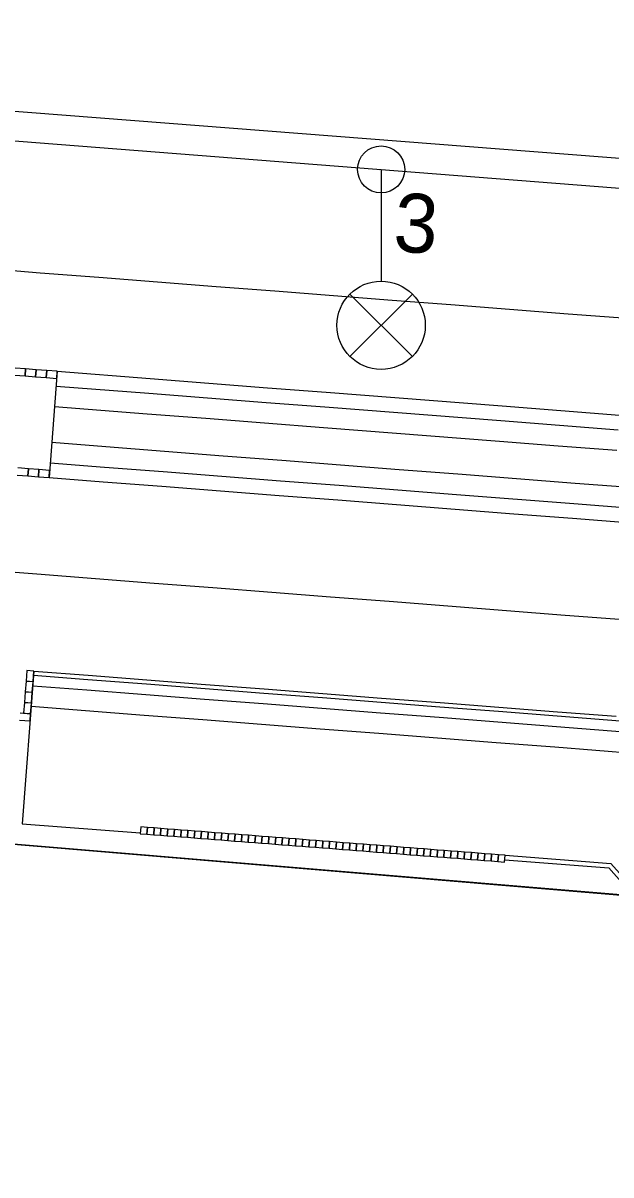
# Model space of a CAD drawing. Extents: x -669628 to -669207, y -977198 to -977075.
# Drawn here: x -669510.73 to -669500.74, y -977152.98 to -977133.39 of the extents above; entities that cross this region are included whole.
import ezdxf

# ---------------------------------------------------------------- set-up
doc = ezdxf.new("R2010")
doc.units = 0
for name, color, linetype in [('SO 01-86-01', 7, 'Continuous'), ('SO 11-10-01', 7, 'Continuous'), ('SO 11-11-01', 7, 'Continuous'), ('SO 11-12-01', 7, 'Continuous'), ('SO 11-12-02', 7, 'Continuous')]:
    doc.layers.add(name, color=color, linetype=linetype)

# ---------------------------------------------------------------- blocks, each defined once
blk = doc.blocks.new('POINT_DISPLAY')
blk.add_line((0, 0), (0, 0))

msp = doc.modelspace()

# ---------------------------------------------------------------- linework, layer by layer
at = {"layer": 'SO 01-86-01'}
for p, q in [((-669519.163, -977134.751), (-669492.657, -977136.821)), ((-669504.645, -977135.881), (-669504.645, -977137.381)), ((-669504.645, -977136.281), (-669504.645, -977137.781)), ((-669505.175, -977138), (-669504.114, -977139.061)), ((-669504.114, -977138), (-669505.175, -977139.061)), ((-669504.645, -977139.281), (-669504.645, -977139.281)), ((-669445.341, -977152.857), (-669517.763, -977146.78)), ((-669445.341, -977152.857), (-669517.763, -977146.78)), ((-669443.485, -977152.976), (-669517.763, -977146.78))]:
    msp.add_line(p, q, dxfattribs=at)
for centre, radius in [((-669504.645, -977135.881), 0.4), ((-669504.645, -977138.531), 0.75)]:
    msp.add_circle(centre, radius, dxfattribs=at)
at = {"layer": 'SO 11-10-01'}
for p, q in [((-669511.434, -977137.559), (-669510.437, -977137.637)), ((-669510.437, -977137.637), (-669509.44, -977137.715)), ((-669509.44, -977137.715), (-669508.443, -977137.792)), ((-669508.443, -977137.792), (-669507.446, -977137.87)), ((-669507.446, -977137.87), (-669506.449, -977137.947)), ((-669506.449, -977137.947), (-669505.452, -977138.025)), ((-669505.452, -977138.025), (-669504.455, -977138.103)), ((-669504.455, -977138.103), (-669503.458, -977138.18)), ((-669503.458, -977138.18), (-669502.461, -977138.258)), ((-669502.461, -977138.258), (-669501.464, -977138.335)), ((-669501.464, -977138.335), (-669500.467, -977138.413)), ((-669511.49, -977142.68), (-669510.493, -977142.758)), ((-669510.493, -977142.758), (-669509.496, -977142.836)), ((-669509.496, -977142.836), (-669508.499, -977142.913)), ((-669508.499, -977142.913), (-669507.502, -977142.991)), ((-669507.502, -977142.991), (-669506.505, -977143.069)), ((-669506.505, -977143.069), (-669505.508, -977143.146)), ((-669505.508, -977143.146), (-669504.511, -977143.224)), ((-669504.511, -977143.224), (-669503.514, -977143.301)), ((-669503.514, -977143.301), (-669502.517, -977143.379)), ((-669502.517, -977143.379), (-669501.52, -977143.457)), ((-669501.52, -977143.457), (-669500.523, -977143.534))]:
    msp.add_line(p, q, dxfattribs=at)
at = {"layer": 'SO 11-11-01'}
msp.add_line((-669495.771, -977136.07), (-669530.167, -977133.393), dxfattribs=at)
at = {"layer": 'SO 11-12-01'}
for p, q in [((-669510.686, -977139.273), (-669510.866, -977139.259)), ((-669510.686, -977139.273), (-669510.696, -977139.392)), ((-669510.696, -977139.392), (-669510.686, -977139.273)), ((-669510.507, -977139.287), (-669510.686, -977139.273)), ((-669510.507, -977139.287), (-669510.516, -977139.406)), ((-669510.516, -977139.406), (-669510.507, -977139.287)), ((-669510.327, -977139.3), (-669510.507, -977139.287)), ((-669510.327, -977139.3), (-669510.337, -977139.42)), ((-669510.337, -977139.42), (-669510.327, -977139.3)), ((-669510.148, -977139.314), (-669510.327, -977139.3)), ((-669510.148, -977139.314), (-669510.288, -977141.119)), ((-669510.157, -977139.434), (-669510.148, -977139.314)), ((-669510.148, -977139.314), (-669508.571, -977139.437)), ((-669510.875, -977139.378), (-669510.696, -977139.392)), ((-669510.696, -977139.392), (-669510.516, -977139.406)), ((-669510.516, -977139.406), (-669510.337, -977139.42)), ((-669510.337, -977139.42), (-669510.157, -977139.434)), ((-669508.571, -977139.437), (-669507.574, -977139.515)), ((-669507.574, -977139.515), (-669506.577, -977139.592)), ((-669510.167, -977139.564), (-669508.591, -977139.686)), ((-669508.591, -977139.686), (-669507.594, -977139.764)), ((-669506.577, -977139.592), (-669505.58, -977139.67)), ((-669505.58, -977139.67), (-669502.589, -977139.903)), ((-669507.594, -977139.764), (-669506.597, -977139.842)), ((-669506.597, -977139.842), (-669505.6, -977139.919)), ((-669502.589, -977139.903), (-669501.592, -977139.98)), ((-669510.195, -977139.913), (-669508.618, -977140.035)), ((-669508.618, -977140.035), (-669507.621, -977140.113)), ((-669505.6, -977139.919), (-669502.609, -977140.152)), ((-669501.592, -977139.98), (-669500.595, -977140.058)), ((-669507.621, -977140.113), (-669506.624, -977140.191)), ((-669506.624, -977140.191), (-669505.627, -977140.268)), ((-669505.627, -977140.268), (-669502.636, -977140.501)), ((-669502.609, -977140.152), (-669501.612, -977140.23)), ((-669501.612, -977140.23), (-669500.615, -977140.307)), ((-669510.242, -977140.521), (-669509.321, -977140.592)), ((-669509.321, -977140.592), (-669508.324, -977140.67)), ((-669508.324, -977140.67), (-669507.327, -977140.748)), ((-669502.636, -977140.501), (-669501.639, -977140.579)), ((-669501.639, -977140.579), (-669500.642, -977140.656)), ((-669510.269, -977140.87), (-669509.348, -977140.941)), ((-669507.327, -977140.748), (-669506.33, -977140.825)), ((-669506.33, -977140.825), (-669505.333, -977140.903)), ((-669510.827, -977141.077), (-669510.647, -977141.091)), ((-669510.638, -977140.971), (-669510.818, -977140.957)), ((-669510.638, -977140.971), (-669510.647, -977141.091)), ((-669510.647, -977141.091), (-669510.638, -977140.971)), ((-669510.459, -977140.985), (-669510.638, -977140.971)), ((-669510.459, -977140.985), (-669510.468, -977141.105)), ((-669510.468, -977141.105), (-669510.459, -977140.985)), ((-669510.279, -977140.999), (-669510.459, -977140.985)), ((-669510.288, -977141.119), (-669510.279, -977140.999)), ((-669509.348, -977140.941), (-669508.351, -977141.019)), ((-669508.351, -977141.019), (-669507.354, -977141.097)), ((-669505.333, -977140.903), (-669504.336, -977140.981)), ((-669504.336, -977140.981), (-669503.339, -977141.058)), ((-669503.339, -977141.058), (-669501.345, -977141.213)), ((-669510.647, -977141.091), (-669510.468, -977141.105)), ((-669510.468, -977141.105), (-669510.288, -977141.119)), ((-669510.288, -977141.119), (-669509.368, -977141.191)), ((-669509.368, -977141.191), (-669508.371, -977141.268)), ((-669508.371, -977141.268), (-669507.374, -977141.346)), ((-669507.354, -977141.097), (-669506.357, -977141.174)), ((-669506.357, -977141.174), (-669505.36, -977141.252)), ((-669505.36, -977141.252), (-669504.363, -977141.329)), ((-669501.345, -977141.213), (-669500.348, -977141.291)), ((-669507.374, -977141.346), (-669506.377, -977141.424)), ((-669506.377, -977141.424), (-669505.38, -977141.501)), ((-669504.363, -977141.329), (-669503.366, -977141.407)), ((-669503.366, -977141.407), (-669501.372, -977141.562)), ((-669505.38, -977141.501), (-669504.383, -977141.579)), ((-669504.383, -977141.579), (-669503.386, -977141.656)), ((-669503.386, -977141.656), (-669502.389, -977141.734)), ((-669501.372, -977141.562), (-669500.375, -977141.64)), ((-669502.389, -977141.734), (-669501.392, -977141.812)), ((-669501.392, -977141.812), (-669500.395, -977141.889)), ((-669510.545, -977144.409), (-669510.747, -977147.008)), ((-669510.664, -977144.4), (-669510.678, -977144.579)), ((-669510.545, -977144.409), (-669510.664, -977144.4)), ((-669510.559, -977144.589), (-669510.545, -977144.409)), ((-669510.545, -977144.409), (-669509.624, -977144.481)), ((-669510.678, -977144.582), (-669510.692, -977144.761)), ((-669510.678, -977144.579), (-669510.559, -977144.589)), ((-669510.559, -977144.591), (-669510.678, -977144.582)), ((-669510.573, -977144.77), (-669510.559, -977144.591)), ((-669510.55, -977144.479), (-669509.629, -977144.551)), ((-669509.629, -977144.551), (-669508.632, -977144.628)), ((-669509.624, -977144.481), (-669508.627, -977144.558)), ((-669508.627, -977144.558), (-669507.63, -977144.636)), ((-669510.693, -977144.764), (-669510.707, -977144.943)), ((-669510.573, -977144.773), (-669510.693, -977144.764)), ((-669510.692, -977144.761), (-669510.573, -977144.77)), ((-669510.587, -977144.952), (-669510.573, -977144.773)), ((-669510.564, -977144.658), (-669509.643, -977144.73)), ((-669509.643, -977144.73), (-669508.646, -977144.808)), ((-669508.632, -977144.628), (-669506.638, -977144.783)), ((-669507.63, -977144.636), (-669506.633, -977144.714)), ((-669506.638, -977144.783), (-669505.641, -977144.861)), ((-669506.633, -977144.714), (-669505.636, -977144.791)), ((-669505.636, -977144.791), (-669504.639, -977144.869)), ((-669510.707, -977144.946), (-669510.721, -977145.125)), ((-669510.707, -977144.943), (-669510.587, -977144.952)), ((-669510.587, -977144.955), (-669510.707, -977144.946)), ((-669510.601, -977145.134), (-669510.587, -977144.955)), ((-669508.646, -977144.808), (-669507.649, -977144.885)), ((-669507.649, -977144.885), (-669506.652, -977144.963)), ((-669506.652, -977144.963), (-669505.655, -977145.04)), ((-669505.641, -977144.861), (-669504.644, -977144.939)), ((-669504.644, -977144.939), (-669503.647, -977145.016)), ((-669504.639, -977144.869), (-669503.642, -977144.946)), ((-669503.642, -977144.946), (-669502.645, -977145.024)), ((-669510.602, -977145.137), (-669510.781, -977145.123)), ((-669510.721, -977145.125), (-669510.601, -977145.134)), ((-669510.611, -977145.256), (-669510.602, -977145.137)), ((-669510.591, -977145.007), (-669509.67, -977145.079)), ((-669509.67, -977145.079), (-669508.673, -977145.157)), ((-669508.673, -977145.157), (-669507.676, -977145.234)), ((-669505.655, -977145.04), (-669504.658, -977145.118)), ((-669504.658, -977145.118), (-669503.661, -977145.196)), ((-669503.661, -977145.196), (-669502.664, -977145.273)), ((-669503.647, -977145.016), (-669502.65, -977145.094)), ((-669502.65, -977145.094), (-669501.653, -977145.171)), ((-669502.645, -977145.024), (-669501.648, -977145.102)), ((-669501.653, -977145.171), (-669498.662, -977145.404)), ((-669501.648, -977145.102), (-669500.651, -977145.179)), ((-669510.791, -977145.242), (-669510.611, -977145.256)), ((-669507.676, -977145.234), (-669506.679, -977145.312)), ((-669506.679, -977145.312), (-669505.682, -977145.389)), ((-669505.682, -977145.389), (-669504.685, -977145.467)), ((-669502.664, -977145.273), (-669501.667, -977145.351)), ((-669501.667, -977145.351), (-669498.676, -977145.584)), ((-669504.685, -977145.467), (-669503.688, -977145.545)), ((-669503.688, -977145.545), (-669502.691, -977145.622)), ((-669502.691, -977145.622), (-669501.694, -977145.7)), ((-669501.694, -977145.7), (-669498.704, -977145.933)), ((-669510.747, -977147.008), (-669508.738, -977147.161)), ((-669508.73, -977147.059), (-669508.739, -977147.174)), ((-669508.615, -977147.068), (-669508.73, -977147.059)), ((-669508.624, -977147.183), (-669508.615, -977147.068)), ((-669508.615, -977147.068), (-669508.624, -977147.183)), ((-669508.501, -977147.077), (-669508.615, -977147.068)), ((-669508.51, -977147.191), (-669508.501, -977147.077)), ((-669508.501, -977147.077), (-669508.51, -977147.191)), ((-669508.386, -977147.086), (-669508.501, -977147.077)), ((-669508.395, -977147.2), (-669508.386, -977147.086)), ((-669508.386, -977147.086), (-669508.395, -977147.2)), ((-669508.271, -977147.095), (-669508.386, -977147.086)), ((-669508.28, -977147.209), (-669508.271, -977147.095)), ((-669508.271, -977147.095), (-669508.28, -977147.209)), ((-669508.157, -977147.104), (-669508.271, -977147.095)), ((-669508.166, -977147.218), (-669508.157, -977147.104)), ((-669508.157, -977147.104), (-669508.166, -977147.218)), ((-669508.042, -977147.112), (-669508.157, -977147.104)), ((-669508.051, -977147.227), (-669508.042, -977147.112)), ((-669508.042, -977147.112), (-669508.051, -977147.227)), ((-669507.927, -977147.121), (-669508.042, -977147.112)), ((-669507.936, -977147.236), (-669507.927, -977147.121)), ((-669507.927, -977147.121), (-669507.936, -977147.236)), ((-669507.813, -977147.13), (-669507.927, -977147.121)), ((-669507.822, -977147.245), (-669507.813, -977147.13)), ((-669507.813, -977147.13), (-669507.822, -977147.245)), ((-669507.698, -977147.139), (-669507.813, -977147.13)), ((-669507.707, -977147.254), (-669507.698, -977147.139)), ((-669507.698, -977147.139), (-669507.707, -977147.254)), ((-669507.584, -977147.148), (-669507.698, -977147.139)), ((-669507.592, -977147.263), (-669507.584, -977147.148)), ((-669507.584, -977147.148), (-669507.592, -977147.263)), ((-669507.469, -977147.157), (-669507.584, -977147.148)), ((-669508.739, -977147.174), (-669508.624, -977147.183)), ((-669508.624, -977147.183), (-669508.51, -977147.191)), ((-669508.51, -977147.191), (-669508.395, -977147.2)), ((-669508.395, -977147.2), (-669508.28, -977147.209)), ((-669508.28, -977147.209), (-669508.166, -977147.218)), ((-669508.166, -977147.218), (-669508.051, -977147.227)), ((-669508.051, -977147.227), (-669507.936, -977147.236)), ((-669507.936, -977147.236), (-669507.822, -977147.245)), ((-669507.822, -977147.245), (-669507.707, -977147.254)), ((-669507.707, -977147.254), (-669507.592, -977147.263)), ((-669507.592, -977147.263), (-669507.478, -977147.272)), ((-669507.478, -977147.272), (-669507.469, -977147.157)), ((-669507.469, -977147.157), (-669507.478, -977147.272)), ((-669507.478, -977147.272), (-669507.363, -977147.281)), ((-669507.354, -977147.166), (-669507.469, -977147.157)), ((-669507.363, -977147.281), (-669507.354, -977147.166)), ((-669507.354, -977147.166), (-669507.363, -977147.281)), ((-669507.363, -977147.281), (-669507.248, -977147.29)), ((-669507.24, -977147.175), (-669507.354, -977147.166)), ((-669507.248, -977147.29), (-669507.24, -977147.175)), ((-669507.24, -977147.175), (-669507.248, -977147.29)), ((-669507.248, -977147.29), (-669507.134, -977147.299)), ((-669507.125, -977147.184), (-669507.24, -977147.175)), ((-669507.134, -977147.299), (-669507.125, -977147.184)), ((-669507.125, -977147.184), (-669507.134, -977147.299)), ((-669507.134, -977147.299), (-669507.019, -977147.307)), ((-669507.01, -977147.193), (-669507.125, -977147.184)), ((-669507.019, -977147.307), (-669507.01, -977147.193)), ((-669507.01, -977147.193), (-669507.019, -977147.307)), ((-669507.019, -977147.307), (-669506.905, -977147.316)), ((-669506.896, -977147.202), (-669507.01, -977147.193)), ((-669506.905, -977147.316), (-669506.896, -977147.202)), ((-669506.896, -977147.202), (-669506.905, -977147.316)), ((-669506.905, -977147.316), (-669506.79, -977147.325)), ((-669506.781, -977147.211), (-669506.896, -977147.202)), ((-669506.79, -977147.325), (-669506.781, -977147.211)), ((-669506.781, -977147.211), (-669506.79, -977147.325)), ((-669506.79, -977147.325), (-669506.675, -977147.334)), ((-669506.666, -977147.22), (-669506.781, -977147.211)), ((-669506.675, -977147.334), (-669506.666, -977147.22)), ((-669506.666, -977147.22), (-669506.675, -977147.334)), ((-669506.675, -977147.334), (-669506.561, -977147.343)), ((-669506.552, -977147.228), (-669506.666, -977147.22)), ((-669506.561, -977147.343), (-669506.552, -977147.228)), ((-669506.552, -977147.228), (-669506.561, -977147.343)), ((-669506.561, -977147.343), (-669506.446, -977147.352)), ((-669506.437, -977147.237), (-669506.552, -977147.228)), ((-669506.446, -977147.352), (-669506.437, -977147.237)), ((-669506.437, -977147.237), (-669506.446, -977147.352)), ((-669506.322, -977147.246), (-669506.437, -977147.237)), ((-669506.331, -977147.361), (-669506.322, -977147.246)), ((-669506.322, -977147.246), (-669506.331, -977147.361)), ((-669506.208, -977147.255), (-669506.322, -977147.246)), ((-669506.217, -977147.37), (-669506.208, -977147.255)), ((-669506.208, -977147.255), (-669506.217, -977147.37)), ((-669506.093, -977147.264), (-669506.208, -977147.255)), ((-669506.102, -977147.379), (-669506.093, -977147.264)), ((-669506.093, -977147.264), (-669506.102, -977147.379)), ((-669505.978, -977147.273), (-669506.093, -977147.264)), ((-669505.987, -977147.388), (-669505.978, -977147.273)), ((-669505.978, -977147.273), (-669505.987, -977147.388)), ((-669505.864, -977147.282), (-669505.978, -977147.273)), ((-669505.873, -977147.397), (-669505.864, -977147.282)), ((-669505.864, -977147.282), (-669505.873, -977147.397)), ((-669505.749, -977147.291), (-669505.864, -977147.282)), ((-669505.758, -977147.406), (-669505.749, -977147.291)), ((-669505.749, -977147.291), (-669505.758, -977147.406)), ((-669505.634, -977147.3), (-669505.749, -977147.291)), ((-669505.643, -977147.415), (-669505.634, -977147.3)), ((-669505.634, -977147.3), (-669505.643, -977147.415)), ((-669505.52, -977147.309), (-669505.634, -977147.3)), ((-669505.529, -977147.423), (-669505.52, -977147.309)), ((-669505.52, -977147.309), (-669505.529, -977147.423)), ((-669505.405, -977147.318), (-669505.52, -977147.309)), ((-669505.414, -977147.432), (-669505.405, -977147.318)), ((-669505.405, -977147.318), (-669505.414, -977147.432)), ((-669505.29, -977147.327), (-669505.405, -977147.318)), ((-669505.299, -977147.441), (-669505.29, -977147.327)), ((-669505.29, -977147.327), (-669505.299, -977147.441)), ((-669505.176, -977147.336), (-669505.29, -977147.327)), ((-669505.185, -977147.45), (-669505.176, -977147.336)), ((-669505.176, -977147.336), (-669505.185, -977147.45)), ((-669505.061, -977147.345), (-669505.176, -977147.336)), ((-669505.07, -977147.459), (-669505.061, -977147.345)), ((-669505.061, -977147.345), (-669505.07, -977147.459)), ((-669504.946, -977147.353), (-669505.061, -977147.345)), ((-669506.446, -977147.352), (-669506.331, -977147.361)), ((-669506.331, -977147.361), (-669506.217, -977147.37)), ((-669506.217, -977147.37), (-669506.102, -977147.379)), ((-669506.102, -977147.379), (-669505.987, -977147.388)), ((-669505.987, -977147.388), (-669505.873, -977147.397)), ((-669505.873, -977147.397), (-669505.758, -977147.406)), ((-669505.758, -977147.406), (-669505.643, -977147.415)), ((-669505.643, -977147.415), (-669505.529, -977147.423)), ((-669505.529, -977147.423), (-669505.414, -977147.432)), ((-669505.414, -977147.432), (-669505.299, -977147.441)), ((-669505.299, -977147.441), (-669505.185, -977147.45)), ((-669505.185, -977147.45), (-669505.07, -977147.459)), ((-669505.07, -977147.459), (-669504.955, -977147.468)), ((-669504.955, -977147.468), (-669504.946, -977147.353)), ((-669504.946, -977147.353), (-669504.955, -977147.468)), ((-669504.955, -977147.468), (-669504.841, -977147.477)), ((-669504.832, -977147.362), (-669504.946, -977147.353)), ((-669504.841, -977147.477), (-669504.832, -977147.362)), ((-669504.832, -977147.362), (-669504.841, -977147.477)), ((-669504.841, -977147.477), (-669504.726, -977147.486)), ((-669504.717, -977147.371), (-669504.832, -977147.362)), ((-669504.726, -977147.486), (-669504.717, -977147.371)), ((-669504.717, -977147.371), (-669504.726, -977147.486)), ((-669504.726, -977147.486), (-669504.611, -977147.495)), ((-669504.603, -977147.38), (-669504.717, -977147.371)), ((-669504.611, -977147.495), (-669504.603, -977147.38)), ((-669504.603, -977147.38), (-669504.611, -977147.495)), ((-669504.611, -977147.495), (-669504.497, -977147.504)), ((-669504.488, -977147.389), (-669504.603, -977147.38)), ((-669504.497, -977147.504), (-669504.488, -977147.389)), ((-669504.488, -977147.389), (-669504.497, -977147.504)), ((-669504.497, -977147.504), (-669504.382, -977147.513)), ((-669504.373, -977147.398), (-669504.488, -977147.389)), ((-669504.382, -977147.513), (-669504.373, -977147.398)), ((-669504.373, -977147.398), (-669504.382, -977147.513)), ((-669504.382, -977147.513), (-669504.267, -977147.522)), ((-669504.259, -977147.407), (-669504.373, -977147.398)), ((-669504.267, -977147.522), (-669504.259, -977147.407)), ((-669504.259, -977147.407), (-669504.267, -977147.522)), ((-669504.267, -977147.522), (-669504.153, -977147.531)), ((-669504.144, -977147.416), (-669504.259, -977147.407)), ((-669504.153, -977147.531), (-669504.144, -977147.416)), ((-669504.144, -977147.416), (-669504.153, -977147.531)), ((-669504.153, -977147.531), (-669504.038, -977147.539)), ((-669504.029, -977147.425), (-669504.144, -977147.416)), ((-669504.038, -977147.539), (-669504.029, -977147.425)), ((-669504.029, -977147.425), (-669504.038, -977147.539)), ((-669504.038, -977147.539), (-669503.924, -977147.548)), ((-669503.915, -977147.434), (-669504.029, -977147.425)), ((-669503.924, -977147.548), (-669503.915, -977147.434)), ((-669503.915, -977147.434), (-669503.924, -977147.548)), ((-669503.8, -977147.443), (-669503.915, -977147.434)), ((-669503.809, -977147.557), (-669503.8, -977147.443)), ((-669503.8, -977147.443), (-669503.809, -977147.557)), ((-669503.685, -977147.452), (-669503.8, -977147.443)), ((-669503.694, -977147.566), (-669503.685, -977147.452)), ((-669503.685, -977147.452), (-669503.694, -977147.566)), ((-669503.571, -977147.461), (-669503.685, -977147.452)), ((-669503.58, -977147.575), (-669503.571, -977147.461)), ((-669503.571, -977147.461), (-669503.58, -977147.575)), ((-669503.456, -977147.469), (-669503.571, -977147.461)), ((-669503.465, -977147.584), (-669503.456, -977147.469)), ((-669503.456, -977147.469), (-669503.465, -977147.584)), ((-669503.341, -977147.478), (-669503.456, -977147.469)), ((-669503.35, -977147.593), (-669503.341, -977147.478)), ((-669503.341, -977147.478), (-669503.35, -977147.593)), ((-669503.227, -977147.487), (-669503.341, -977147.478)), ((-669503.236, -977147.602), (-669503.227, -977147.487)), ((-669503.227, -977147.487), (-669503.236, -977147.602)), ((-669503.112, -977147.496), (-669503.227, -977147.487)), ((-669503.121, -977147.611), (-669503.112, -977147.496)), ((-669503.112, -977147.496), (-669503.121, -977147.611)), ((-669502.997, -977147.505), (-669503.112, -977147.496)), ((-669503.006, -977147.62), (-669502.997, -977147.505)), ((-669502.997, -977147.505), (-669503.006, -977147.62)), ((-669502.883, -977147.514), (-669502.997, -977147.505)), ((-669502.883, -977147.514), (-669502.892, -977147.629)), ((-669502.892, -977147.629), (-669502.883, -977147.514)), ((-669502.768, -977147.523), (-669502.883, -977147.514)), ((-669502.768, -977147.523), (-669502.777, -977147.638)), ((-669502.777, -977147.638), (-669502.768, -977147.523)), ((-669502.653, -977147.532), (-669502.768, -977147.523)), ((-669502.653, -977147.532), (-669502.662, -977147.647)), ((-669502.662, -977147.647), (-669502.653, -977147.532)), ((-669502.539, -977147.541), (-669502.653, -977147.532)), ((-669502.548, -977147.656), (-669502.539, -977147.541)), ((-669502.539, -977147.54), (-669500.74, -977147.68)), ((-669503.924, -977147.548), (-669503.809, -977147.557)), ((-669503.809, -977147.557), (-669503.694, -977147.566)), ((-669503.694, -977147.566), (-669503.58, -977147.575)), ((-669503.58, -977147.575), (-669503.465, -977147.584)), ((-669503.465, -977147.584), (-669503.35, -977147.593)), ((-669503.35, -977147.593), (-669503.236, -977147.602)), ((-669503.236, -977147.602), (-669503.121, -977147.611)), ((-669503.121, -977147.611), (-669503.006, -977147.62)), ((-669503.006, -977147.62), (-669502.892, -977147.629)), ((-669502.892, -977147.629), (-669502.777, -977147.638)), ((-669502.777, -977147.638), (-669502.662, -977147.647)), ((-669502.662, -977147.647), (-669502.548, -977147.656)), ((-669502.545, -977147.62), (-669500.778, -977147.757))]:
    msp.add_line(p, q, dxfattribs=at)
at = {"layer": 'SO 11-12-02'}
for p, q in [((-669497.053, -977151.836), (-669500.74, -977147.68)), ((-669497.059, -977151.95), (-669500.778, -977147.757))]:
    msp.add_line(p, q, dxfattribs=at)

# ---------------------------------------------------------------- block references
at = {"layer": 'SO 01-86-01', "rotation": 4.450857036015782}
msp.add_blockref('POINT_DISPLAY', (-669504.675, -977135.896), dxfattribs=at)

# ---------------------------------------------------------------- texts
at = {"layer": 'SO 01-86-01'}
msp.add_text('3', height=1, rotation=356.1, dxfattribs=at).set_placement((-669504.454, -977137.27))

doc.saveas('drawing.dxf')
